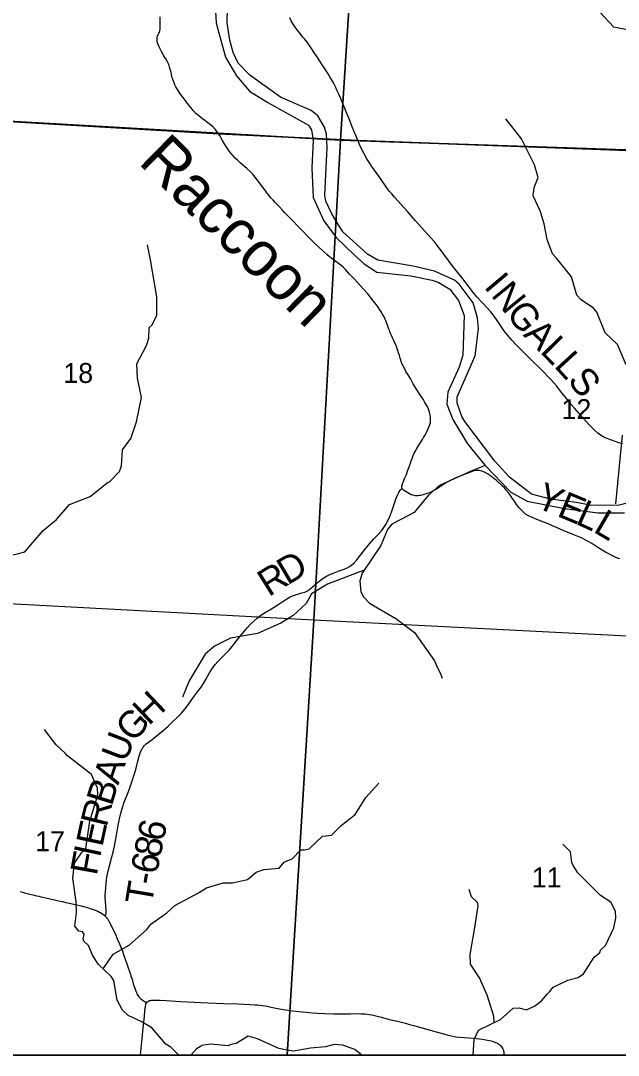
# Model space of a CAD drawing. Extents: x 0 to 34, y 0 to 22.
# Drawn here: x 24.638 to 25.892, y 14.1 to 16.271 of the extents above; entities that cross this region are included whole.
import ezdxf

# ---------------------------------------------------------------- set-up
doc = ezdxf.new("R2010")
doc.units = 0
for name, color, linetype in [('Default', 7, 'Continuous'), ('GM_X_County_Road', 7, 'Continuous'), ('GM_X_County_Road_Text', 7, 'Continuous'), ('GM_X_Major_River', 7, 'Continuous'), ('GM_X_Major_River_Text', 7, 'Continuous'), ('GM_X_Minor_River', 7, 'Continuous'), ('GM_X_Section', 7, 'Continuous'), ('GM_X_Section_Text', 7, 'Continuous'), ('GM_X_Township_Road', 7, 'Continuous'), ('GM_X_Township_Road_Text', 7, 'Continuous'), ('SH_Data', 7, 'Continuous'), ('SH_Text', 7, 'Continuous')]:
    doc.layers.add(name, color=color, linetype=linetype)

msp = doc.modelspace()

# ---------------------------------------------------------------- linework, layer by layer
at = {"layer": 'Default'}
msp.add_lwpolyline([(27.7198, 20.9), (23.5167, 20.9), (23.5167, 16.1239), (23.5888, 16.1195), (25.0535, 16.0331), (25.3458, 16.0191), (26.0811, 15.9921), (26.3691, 15.9829), (26.8773, 15.953), (26.8866, 15.9536), (26.8953, 15.9537)], dxfattribs=at)
for points in [[(23.5167, 16.1239), (23.5167, 14.1), (26.2331, 14.1), (26.29, 15.0246), (26.3153, 15.3279), (26.3625, 15.9099), (26.3691, 15.9829), (26.0811, 15.9921), (25.3458, 16.0191), (25.0535, 16.0331), (23.5888, 16.1195)], [(24.1517, 14.1), (25.1974, 14.1), (25.2534, 15.0128), (24.2076, 15.0689)], [(25.1974, 14.1), (26.2424, 14.1), (26.2944, 14.9601), (25.2534, 15.0128)]]:
    msp.add_lwpolyline(points, close=True, dxfattribs=at)
at = {"layer": 'GM_X_County_Road'}
for points in [[(25.346, 16.0186), (25.3384, 16.0361), (25.3322, 16.0517), (25.3286, 16.0609), (25.3252, 16.0696), (25.3227, 16.0758), (25.309, 16.1087), (25.3056, 16.1165), (25.3017, 16.1252), (25.2986, 16.132), (25.2957, 16.1375), (25.2921, 16.144), (25.287, 16.1526), (25.283, 16.1589), (25.2741, 16.173), (25.271, 16.1777), (25.2674, 16.1835), (25.259, 16.1966), (25.2562, 16.2007), (25.2452, 16.2165), (25.2389, 16.2254), (25.2333, 16.2324), (25.2303, 16.2364), (25.2268, 16.2408), (25.2217, 16.2469), (25.2181, 16.2512), (25.2139, 16.2573), (25.2097, 16.2636), (25.2056, 16.2704), (25.203, 16.2764)], [(25.7998, 15.4575), (25.7992, 15.4582), (25.7927, 15.4657), (25.783, 15.4778), (25.7709, 15.4936), (25.7619, 15.5048), (25.7517, 15.5165), (25.7436, 15.5251), (25.7371, 15.5319), (25.727, 15.5419), (25.7114, 15.5571), (25.6902, 15.578), (25.6784, 15.5899), (25.6686, 15.6003), (25.6612, 15.6086), (25.6575, 15.6134), (25.654, 15.6179), (25.6489, 15.6251), (25.644, 15.6324), (25.6377, 15.6414), (25.6317, 15.6505), (25.6245, 15.6595), (25.6166, 15.6684), (25.6043, 15.6815), (25.595, 15.6915), (25.5882, 15.6996), (25.5794, 15.7112), (25.5747, 15.7173), (25.5676, 15.7265), (25.5633, 15.7321), (25.5551, 15.7422), (25.5453, 15.7543), (25.5261, 15.7806), (25.5203, 15.7883), (25.5119, 15.7991), (25.5069, 15.8058), (25.4979, 15.8159), (25.4796, 15.836), (25.4664, 15.851), (25.4496, 15.8703), (25.4223, 15.9006), (25.4166, 15.9071), (25.412, 15.9123), (25.408, 15.9178), (25.4048, 15.9222), (25.3956, 15.9356), (25.3892, 15.9447), (25.3838, 15.9524), (25.3786, 15.9597), (25.3744, 15.9656), (25.3698, 15.9722), (25.3647, 15.9807), (25.3582, 15.9927), (25.3535, 16.0021), (25.3493, 16.0111), (25.346, 16.0186)], [(25.9013, 15.3826), (25.8912, 15.3859), (25.8871, 15.3872), (25.8754, 15.3913), (25.8685, 15.3939), (25.8617, 15.397), (25.8548, 15.401), (25.8489, 15.4054), (25.8423, 15.4111), (25.8323, 15.4212), (25.8181, 15.4369), (25.8099, 15.4462), (25.7998, 15.4575)], [(24.6371, 14.4437), (24.6419, 14.442), (24.6481, 14.4402), (24.652, 14.4392), (24.6571, 14.438), (24.6638, 14.4365), (24.6688, 14.4354), (24.6718, 14.4348), (24.6766, 14.4338), (24.6807, 14.4327), (24.6849, 14.4318), (24.6909, 14.4304), (24.7095, 14.4262), (24.7179, 14.4243), (24.7263, 14.4225), (24.7333, 14.4209), (24.7397, 14.4195), (24.7498, 14.4172), (24.7558, 14.4158), (24.7624, 14.4142), (24.769, 14.4125), (24.7761, 14.4105), (24.7883, 14.4065), (24.7945, 14.4043), (24.8, 14.4021), (24.8035, 14.4005), (24.8066, 14.3989), (24.8097, 14.3971), (24.8122, 14.3954), (24.8145, 14.3935), (24.8158, 14.3922), (24.8176, 14.3901), (24.8193, 14.3878), (24.8208, 14.3853), (24.8238, 14.3799), (24.8293, 14.3692), (24.8328, 14.362), (24.8369, 14.3539), (24.8408, 14.3445), (24.8454, 14.3342), (24.8469, 14.3305), (24.8485, 14.3264), (24.8501, 14.3224), (24.8523, 14.3167), (24.8542, 14.3114), (24.8608, 14.2922), (24.8644, 14.2817), (24.8683, 14.2703), (24.8696, 14.2662), (24.8718, 14.2597), (24.8745, 14.2503), (24.8758, 14.2461), (24.8776, 14.241), (24.8796, 14.2349), (24.8809, 14.2319), (24.8819, 14.2293), (24.8834, 14.2266), (24.8846, 14.2247), (24.886, 14.2229), (24.8874, 14.2211), (24.8898, 14.2189), (24.8934, 14.2162), (24.9012, 14.2109), (24.9024, 14.2101)], [(24.8894, 14.1), (24.893, 14.1352), (24.8953, 14.1575), (24.8978, 14.1816), (24.8988, 14.1938), (24.9001, 14.2034), (24.9006, 14.2057), (24.901, 14.2075), (24.9018, 14.2092), (24.9024, 14.2101)], [(24.9024, 14.2101), (24.9039, 14.2119), (24.9053, 14.213), (24.9069, 14.214), (24.9087, 14.2148), (24.9106, 14.2153), (24.9129, 14.2156), (24.9155, 14.2158), (24.9192, 14.2159), (24.9305, 14.2155), (24.9443, 14.2147), (24.9732, 14.2129), (25.0025, 14.2112), (25.0306, 14.2099), (25.0639, 14.2086), (25.0937, 14.2077), (25.1192, 14.2067), (25.1291, 14.2061), (25.1346, 14.2058), (25.1401, 14.2052), (25.1512, 14.2035), (25.167, 14.2006), (25.181, 14.1978), (25.1939, 14.1956), (25.2082, 14.1936), (25.2219, 14.1919), (25.2369, 14.1902), (25.2434, 14.1896), (25.2495, 14.1891), (25.2606, 14.1885), (25.2761, 14.1879), (25.2948, 14.1873), (25.3135, 14.187), (25.3302, 14.1873), (25.3424, 14.1875), (25.3526, 14.1872), (25.3599, 14.1869), (25.3661, 14.1864), (25.3703, 14.1858), (25.3751, 14.1849), (25.3915, 14.181), (25.4149, 14.1747), (25.4286, 14.1713), (25.4452, 14.1672), (25.4542, 14.1649), (25.4631, 14.1625), (25.4846, 14.1565), (25.5095, 14.1495), (25.5326, 14.1431), (25.5385, 14.1415), (25.5451, 14.14), (25.5513, 14.139), (25.5587, 14.1382), (25.5786, 14.1369), (25.5884, 14.136), (25.6006, 14.1346), (25.6068, 14.1338), (25.614, 14.1326), (25.6208, 14.1313), (25.6253, 14.1302), (25.6285, 14.1292), (25.6315, 14.1282), (25.6345, 14.127), (25.6371, 14.1259), (25.6393, 14.1247), (25.6415, 14.1233), (25.6434, 14.1218), (25.6454, 14.1198), (25.647, 14.1177), (25.6485, 14.1156), (25.6498, 14.1134), (25.6507, 14.1111), (25.6512, 14.109), (25.6515, 14.1067), (25.6518, 14.1035), (25.6519, 14.1)]]:
    msp.add_lwpolyline(points, dxfattribs=at)
at = {"layer": 'GM_X_Major_River'}
for points in [[(25.6326, 15.3467), (25.5696, 15.4298), (25.5635, 15.44), (25.5536, 15.4684), (25.5536, 15.4813), (25.5916, 15.5672), (25.5983, 15.6249), (25.5963, 15.6469), (25.5871, 15.6784), (25.5582, 15.7181), (25.548, 15.7261), (25.5062, 15.7453), (25.4619, 15.7557), (25.3876, 15.7684), (25.3656, 15.7808), (25.3143, 15.8277), (25.2979, 15.8538), (25.2907, 15.8656), (25.2781, 15.8921), (25.2766, 15.9046), (25.2812, 16.0048), (25.28, 16.0325), (25.2758, 16.0469), (25.2613, 16.0707), (25.2477, 16.0825), (25.1836, 16.1103), (25.1187, 16.156), (25.0943, 16.1817), (25.084, 16.2041), (25.0768, 16.2298), (25.0714, 16.2662), (25.0727, 16.3289)], [(25.0459, 16.3018), (25.0486, 16.2662), (25.0517, 16.2525), (25.0682, 16.1941), (25.091, 16.1547), (25.1184, 16.123), (25.1567, 16.0988), (25.2417, 16.0517), (25.2482, 16.0419), (25.2516, 16.0199), (25.2491, 15.9618), (25.2516, 15.8999), (25.2741, 15.8507), (25.3003, 15.8155), (25.3368, 15.7803), (25.3588, 15.7607), (25.3854, 15.7433), (25.457, 15.7356), (25.5017, 15.7259), (25.5139, 15.7222), (25.5385, 15.7074), (25.5568, 15.6836), (25.5686, 15.6518), (25.5658, 15.5687), (25.5583, 15.544), (25.5346, 15.4915), (25.532, 15.4661), (25.5446, 15.4339), (25.5755, 15.3827), (25.6126, 15.3376)], [(25.95, 15.2684), (25.8906, 15.2535), (25.8319, 15.254), (25.8043, 15.26), (25.7494, 15.2671), (25.71, 15.2772), (25.6634, 15.3127), (25.6326, 15.3467)], [(25.6126, 15.3376), (25.6665, 15.2812), (25.7006, 15.2624), (25.779, 15.2471), (25.8498, 15.2382), (25.9046, 15.2383)]]:
    msp.add_lwpolyline(points, dxfattribs=at)
at = {"layer": 'GM_X_Minor_River'}
for points in [[(26.1935, 16.3026), (26.1966, 16.2917), (26.1235, 16.2558), (26.036, 16.2415), (26.0085, 16.2365), (25.9717, 16.2351), (25.9486, 16.2438), (25.8827, 16.2572), (25.8535, 16.288), (25.8155, 16.3387), (25.8045, 16.3689)], [(25.9083, 15.5485), (25.8901, 15.5914), (25.8644, 15.6154), (25.8466, 15.6594), (25.8401, 15.6678), (25.814, 15.6853), (25.8049, 15.6948), (25.7939, 15.7335), (25.7624, 15.7723), (25.7537, 15.7814), (25.7424, 15.8114), (25.7367, 15.8441), (25.7291, 15.8673), (25.7272, 15.873), (25.7136, 15.9034), (25.7155, 15.9205), (25.7238, 15.9418), (25.7159, 15.9684), (25.689, 16.0228), (25.656, 16.0649)], [(24.8495, 15.3367), (24.8517, 15.3702), (24.8692, 15.3942), (24.8813, 15.4288), (24.8916, 15.4801), (24.8836, 15.5204), (24.8818, 15.5505), (24.9022, 15.5893), (24.9068, 15.6049), (24.9076, 15.6269), (24.914, 15.6326), (24.9239, 15.6528), (24.9235, 15.6916), (24.9103, 15.7687), (24.9042, 15.8007)], [(25.8868, 15.2567), (25.9007, 15.4013)], [(24.419, 15.219), (24.446, 15.2199), (24.4815, 15.1949), (24.4905, 15.1919), (24.5181, 15.1914), (24.5252, 15.1893), (24.5481, 15.1722), (24.5943, 15.1499), (24.6147, 15.1477), (24.6471, 15.1565), (24.6851, 15.2013), (24.7134, 15.2239), (24.7408, 15.2553), (24.784, 15.2725), (24.82, 15.301), (24.8246, 15.3031), (24.8453, 15.3249), (24.8495, 15.3368)], [(25.6126, 15.3376), (25.5843, 15.326), (25.5165, 15.2957), (25.4928, 15.2743), (25.4638, 15.2385), (25.452, 15.2323), (25.4168, 15.2143), (25.4074, 15.2032), (25.3936, 15.1698), (25.3549, 15.1115), (25.3496, 15.0955), (25.3521, 15.0727), (25.3574, 15.0617), (25.37, 15.0489), (25.4253, 15.0165), (25.4645, 14.9871), (25.5063, 14.9273), (25.5117, 14.9144), (25.5174, 14.9038), (25.5224, 14.8913)], [(25.3589, 15.1175), (25.2818, 15.0883), (25.2485, 15.068), (25.2368, 15.0478), (25.2097, 15.023), (25.184, 15.0069), (25.1348, 14.9846), (25.0783, 14.9749), (25.045, 14.9584), (25.025, 14.9419), (24.9919, 14.8856), (24.9777, 14.8513)], [(24.9701, 14.1), (24.9531, 14.1169), (24.9427, 14.1233), (24.9131, 14.1577), (24.8912, 14.1709), (24.864, 14.1832), (24.8515, 14.1946), (24.8408, 14.2158), (24.8334, 14.2567), (24.8279, 14.2652), (24.8015, 14.2904), (24.7896, 14.3086), (24.7808, 14.3305), (24.7705, 14.3392), (24.7695, 14.3445), (24.7717, 14.3543), (24.7677, 14.359), (24.7601, 14.3604), (24.7518, 14.3709), (24.7553, 14.3989), (24.7545, 14.4221), (24.7476, 14.4713), (24.7512, 14.5031), (24.7659, 14.5246), (24.7752, 14.5338), (24.7834, 14.5913), (24.8002, 14.6466), (24.7995, 14.6607), (24.7867, 14.6892), (24.7365, 14.7284), (24.7321, 14.7331), (24.7127, 14.7515), (24.6883, 14.7838)], [(24.8111, 14.2813), (24.8324, 14.3121), (24.8655, 14.3308), (24.9028, 14.3638), (24.911, 14.375), (24.945, 14.3986), (24.9614, 14.4144), (25.0113, 14.4412), (25.0279, 14.4517), (25.0633, 14.4616), (25.0826, 14.4621), (25.1142, 14.4691), (25.1324, 14.4845), (25.1481, 14.4897), (25.1807, 14.4924), (25.1917, 14.5057), (25.2074, 14.5121), (25.2261, 14.5312), (25.2329, 14.5314), (25.2435, 14.5329), (25.2716, 14.5598), (25.2905, 14.5618), (25.3104, 14.5824), (25.3398, 14.605), (25.3625, 14.6412), (25.3895, 14.6711)], [(25.5876, 14.1), (25.5876, 14.1001), (25.5894, 14.1334), (25.5987, 14.1525), (25.6447, 14.1753), (25.6715, 14.1988), (25.6836, 14.1995), (25.6986, 14.1956), (25.7159, 14.203), (25.7306, 14.214), (25.7435, 14.2287), (25.7478, 14.2332), (25.7549, 14.2428), (25.7859, 14.2574), (25.808, 14.2635), (25.8192, 14.2708), (25.8411, 14.3061), (25.8531, 14.3156), (25.8548, 14.3209), (25.8649, 14.3304), (25.8826, 14.3675), (25.8866, 14.3878), (25.8859, 14.4023), (25.8763, 14.4212), (25.8545, 14.4356), (25.8071, 14.4827), (25.797, 14.4985), (25.7945, 14.5043), (25.7914, 14.5268), (25.7753, 14.5433)], [(25.6312, 14.1686), (25.6306, 14.1822), (25.6168, 14.2263), (25.6005, 14.2626), (25.5817, 14.2909), (25.5812, 14.3114), (25.5908, 14.3684), (25.5979, 14.4138), (25.5962, 14.4203), (25.5841, 14.4328), (25.5789, 14.4482)], [(25.354, 14.1), (25.3391, 14.1125), (25.3137, 14.1216), (25.296, 14.1227), (25.2775, 14.1177), (25.2461, 14.1153), (25.2102, 14.1088), (25.2004, 14.1103), (25.1796, 14.1144), (25.1349, 14.1345), (25.1153, 14.1401), (25.0903, 14.1245), (25.0794, 14.1225), (25.0737, 14.1199), (25.037, 14.1232), (25.0174, 14.1209), (25.0151, 14.1182), (25.0072, 14.1133), (24.9952, 14.1)]]:
    msp.add_lwpolyline(points, dxfattribs=at)
at = {"layer": 'GM_X_Section'}
for points in [[(24.3357, 17.1007), (25.3722, 17.0086), (25.3091, 16.0203), (24.2716, 16.0795)], [(26.4248, 16.9831), (26.3613, 15.9846), (25.3091, 16.0203), (25.3722, 17.0086), (25.8848, 17.0085)], [(24.2716, 16.0795), (25.3091, 16.0203), (25.2534, 15.0128), (24.2076, 15.0689)], [(25.3091, 16.0203), (26.3613, 15.9846), (26.3734, 15.9843), (26.2944, 14.9601), (25.2534, 15.0128)]]:
    msp.add_lwpolyline(points, close=True, dxfattribs=at)
at = {"layer": 'GM_X_Township_Road'}
for points in [[(24.9421, 16.1912), (24.9387, 16.1966), (24.9335, 16.2063), (24.9287, 16.2155), (24.9258, 16.222), (24.9248, 16.2263), (24.9244, 16.2307), (24.9247, 16.2352), (24.9253, 16.2383), (24.9267, 16.2418), (24.9282, 16.2446), (24.9293, 16.2467), (24.9303, 16.2496), (24.9308, 16.2532), (24.9308, 16.2599), (24.9307, 16.2705), (24.9306, 16.2785)], [(25.0526, 16.0342), (25.0499, 16.0383), (25.0461, 16.0431), (25.0418, 16.0475), (25.0366, 16.0519), (25.0278, 16.0587), (25.0258, 16.0602), (25.0223, 16.0627), (25.0124, 16.0702), (25.0059, 16.076), (25.0002, 16.0819), (24.9952, 16.0882), (24.9885, 16.0972), (24.9833, 16.1041), (24.9783, 16.1105), (24.9733, 16.1168), (24.9708, 16.1205), (24.9684, 16.1241), (24.9659, 16.1284), (24.9638, 16.1322), (24.9618, 16.1363), (24.96, 16.1401), (24.9571, 16.1477), (24.9562, 16.1508), (24.9552, 16.1543), (24.9545, 16.1578), (24.9536, 16.1616), (24.9525, 16.167), (24.9507, 16.173), (24.9488, 16.1785), (24.9461, 16.1842), (24.9427, 16.1903), (24.9421, 16.1912)], [(25.8952, 15.1415), (25.887, 15.1444), (25.8785, 15.1484), (25.8717, 15.152), (25.8647, 15.1557), (25.8491, 15.1657), (25.8364, 15.1737), (25.8261, 15.1796), (25.816, 15.1847), (25.7987, 15.1918), (25.7762, 15.2013), (25.7413, 15.2164), (25.7299, 15.2209), (25.7176, 15.2257), (25.7135, 15.2273), (25.7101, 15.2287), (25.7033, 15.232), (25.6975, 15.2356), (25.6936, 15.2387), (25.6899, 15.2421), (25.6844, 15.248), (25.6814, 15.2519), (25.6784, 15.2558), (25.6738, 15.2625), (25.6705, 15.2671), (25.6669, 15.2724), (25.6619, 15.2794), (25.6569, 15.2856), (25.6528, 15.2903), (25.6488, 15.2943), (25.6453, 15.2976), (25.6395, 15.3032), (25.6354, 15.3067), (25.6311, 15.3104), (25.6238, 15.316), (25.6176, 15.3199), (25.611, 15.3232), (25.6058, 15.3253), (25.6005, 15.3267), (25.5963, 15.3271), (25.592, 15.3268), (25.5867, 15.3255), (25.578, 15.3223), (25.5653, 15.3172), (25.5494, 15.3107), (25.5394, 15.3057), (25.5292, 15.3002), (25.5092, 15.2869), (25.5015, 15.2828), (25.494, 15.2796), (25.489, 15.278), (25.484, 15.2763), (25.4802, 15.2754), (25.4773, 15.2747), (25.4742, 15.2742), (25.4711, 15.2738), (25.466, 15.2738), (25.4629, 15.2743), (25.4603, 15.2749), (25.4575, 15.2761), (25.4437, 15.2845), (25.4416, 15.286), (25.4399, 15.2874), (25.4391, 15.2885), (25.4385, 15.2896), (25.438, 15.2911), (25.4379, 15.293), (25.4381, 15.2949), (25.4383, 15.2967), (25.4389, 15.2986), (25.4411, 15.3042), (25.4422, 15.3067), (25.4448, 15.3126), (25.4474, 15.3187), (25.4507, 15.3278), (25.4534, 15.3349), (25.4552, 15.3404), (25.4575, 15.3473), (25.4592, 15.3523), (25.461, 15.3573), (25.4636, 15.3636), (25.4654, 15.3669), (25.4682, 15.3717), (25.4734, 15.3802), (25.4761, 15.3843), (25.4781, 15.3875), (25.481, 15.3922), (25.4832, 15.3959), (25.4861, 15.4007), (25.4908, 15.4094), (25.494, 15.4161), (25.4959, 15.4213), (25.4976, 15.4279), (25.4982, 15.4333), (25.4982, 15.4382), (25.4975, 15.4436), (25.4959, 15.4496), (25.4938, 15.4553), (25.4908, 15.4618), (25.4863, 15.4697), (25.4822, 15.4768), (25.4743, 15.4887), (25.4619, 15.5089), (25.4559, 15.5197), (25.4496, 15.5297), (25.4472, 15.5334), (25.4439, 15.5399), (25.4431, 15.5415), (25.4419, 15.5437), (25.4396, 15.548), (25.4385, 15.5501), (25.4375, 15.5521), (25.4363, 15.5556), (25.4354, 15.5591), (25.4344, 15.5628), (25.4327, 15.5682), (25.431, 15.574), (25.4294, 15.5787), (25.428, 15.5824), (25.4263, 15.5868), (25.4201, 15.6009), (25.4181, 15.6055), (25.416, 15.6104), (25.4148, 15.6131), (25.4136, 15.6161), (25.4123, 15.6193), (25.4107, 15.6232), (25.4075, 15.6321), (25.4044, 15.6406), (25.4005, 15.649), (25.3972, 15.6552), (25.3945, 15.6596), (25.3918, 15.6642), (25.3881, 15.6695), (25.3847, 15.6744), (25.3814, 15.6786), (25.3764, 15.6852), (25.3668, 15.6974), (25.3564, 15.7084), (25.3385, 15.7283), (25.3281, 15.7387), (25.3199, 15.7483), (25.3147, 15.7538), (25.3097, 15.7579), (25.3028, 15.7629), (25.2993, 15.7655), (25.296, 15.7681), (25.2927, 15.7705), (25.2882, 15.7739), (25.2863, 15.7754), (25.2807, 15.7803), (25.2794, 15.7815), (25.2729, 15.7874), (25.2532, 15.8053), (25.2457, 15.8128), (25.225, 15.8342), (25.2045, 15.8556), (25.1988, 15.8613), (25.1919, 15.8685), (25.1868, 15.8739), (25.1802, 15.8806), (25.173, 15.8882), (25.1676, 15.894), (25.1632, 15.899), (25.158, 15.9056), (25.1548, 15.9098), (25.1523, 15.9131), (25.1456, 15.922), (25.1427, 15.9257), (25.139, 15.9304), (25.1342, 15.9366), (25.1294, 15.943), (25.1252, 15.9483), (25.1201, 15.9537), (25.1128, 15.9603), (25.1033, 15.9684), (25.0987, 15.9725), (25.0937, 15.9772), (25.0885, 15.9825), (25.0836, 15.9879), (25.0766, 15.9963), (25.0704, 16.0045), (25.0665, 16.0106), (25.0617, 16.0191), (25.055, 16.0307), (25.0537, 16.0326), (25.0526, 16.0342)], [(24.8158, 14.3922), (24.817, 14.3956), (24.8174, 14.3978), (24.8176, 14.4001), (24.8175, 14.4028), (24.816, 14.4241), (24.8158, 14.4301), (24.8158, 14.4361), (24.8168, 14.4515), (24.8176, 14.4607), (24.8193, 14.4742), (24.8217, 14.487), (24.8243, 14.4978), (24.8288, 14.5133), (24.8322, 14.526), (24.8348, 14.5388), (24.839, 14.562), (24.8418, 14.5786), (24.8454, 14.5962), (24.8483, 14.6083), (24.8517, 14.6201), (24.8556, 14.6312), (24.8645, 14.6536), (24.8682, 14.6635), (24.8716, 14.6735), (24.8743, 14.6818), (24.8769, 14.6907), (24.8802, 14.7027), (24.8833, 14.714), (24.887, 14.7278), (24.8898, 14.7367), (24.8921, 14.7417), (24.8947, 14.7459), (24.8982, 14.7501), (24.9017, 14.7535), (24.9142, 14.7626), (24.922, 14.7687), (24.9368, 14.7811), (24.9474, 14.7907), (24.9574, 14.8), (24.9662, 14.8086), (24.9696, 14.8118), (24.9748, 14.8171), (24.9825, 14.826), (24.9897, 14.8354), (24.9958, 14.8441), (25.0031, 14.8541), (25.0072, 14.8596), (25.0146, 14.8696), (25.0181, 14.8747), (25.0214, 14.88), (25.0265, 14.8886), (25.0345, 14.9026), (25.0409, 14.9124), (25.0465, 14.9199), (25.0518, 14.9259), (25.0661, 14.9404), (25.0755, 14.9503), (25.084, 14.9602), (25.0989, 14.9792), (25.107, 14.9893), (25.1139, 14.9973), (25.1199, 15.0036), (25.1277, 15.0115), (25.1341, 15.0174), (25.1385, 15.0208), (25.1441, 15.0247), (25.1662, 15.0382), (25.1818, 15.0482), (25.1901, 15.0537), (25.1963, 15.0577), (25.2033, 15.0616), (25.2106, 15.0649), (25.2187, 15.0678), (25.2277, 15.0701), (25.2344, 15.0718), (25.2384, 15.0736), (25.2427, 15.0762), (25.2457, 15.0785), (25.2499, 15.082), (25.2537, 15.0855), (25.2603, 15.0915), (25.2664, 15.0964), (25.2729, 15.1009), (25.2797, 15.1051), (25.2869, 15.1088), (25.296, 15.1125), (25.3065, 15.1163), (25.3171, 15.1199), (25.3228, 15.1224), (25.3277, 15.1252), (25.3322, 15.1284), (25.3378, 15.1334), (25.3432, 15.1394), (25.3509, 15.1491), (25.3599, 15.1609), (25.3702, 15.1733), (25.3793, 15.1833), (25.3866, 15.191), (25.3949, 15.2003), (25.4002, 15.2072), (25.4044, 15.2134), (25.4086, 15.2211), (25.4126, 15.2302), (25.417, 15.2418), (25.4228, 15.2602), (25.4257, 15.269), (25.4292, 15.2769), (25.4312, 15.2806), (25.4333, 15.2842), (25.436, 15.2873), (25.4385, 15.2896)]]:
    msp.add_lwpolyline(points, dxfattribs=at)
at = {"layer": 'SH_Data'}
msp.add_lwpolyline([(23.5167, 20.9), (30.3167, 20.9), (30.3167, 14.1), (23.5167, 14.1)], close=True, dxfattribs=at)
at = {"layer": 'SH_Text'}
msp.add_lwpolyline([(30.3167, 20.9), (23.5167, 20.9), (23.5167, 14.1), (29.5051, 14.1)], dxfattribs=at)

# ---------------------------------------------------------------- texts
at = {"layer": 'GM_X_County_Road_Text'}
for s, rotation, p in [('I', 310.1619, (25.6085, 15.7119)), ('N', 309.1815, (25.6234, 15.6942)), ('G', 307.9566, (25.6548, 15.6557)), ('A', 315.0572, (25.6907, 15.6106)), ('L', 314.6167, (25.726, 15.5753)), ('L', 312.4173, (25.7554, 15.5455)), ('S', 309.6705, (25.7836, 15.5147))]:
    msp.add_text(s, height=0.0568, rotation=rotation, dxfattribs=at).set_placement(p)
at = {"layer": 'GM_X_Major_River_Text'}
msp.add_text('Raccoon', height=0.0947, rotation=315.5119, dxfattribs=at).set_placement((24.8827, 15.9724))
at = {"layer": 'GM_X_Section_Text'}
for s, p in [('18', (24.7279, 15.5106)), ('12', (25.7729, 15.4347)), ('17', (24.6687, 14.5282)), ('11', (25.7104, 14.4523))]:
    msp.add_text(s, height=0.04186, rotation=0, dxfattribs=at).set_placement(p)
at = {"layer": 'GM_X_Township_Road_Text'}
for s, rotation, p in [('Y', 337.4034, (25.7149, 15.2513)), ('E', 337.3228, (25.7611, 15.2321)), ('L', 335.5532, (25.7999, 15.2159)), ('L', 329.6834, (25.8372, 15.1991)), ('D', 30.5858, (25.1978, 15.0854)), ('R', 31.935, (25.1585, 15.0609)), ('H', 43.4942, (24.9068, 14.7902)), ('G', 47.346, (24.8737, 14.7542)), ('U', 69.0963, (24.8588, 14.7123)), ('A', 71.307, (24.843, 14.6655)), ('B', 72.6895, (24.8292, 14.6213)), ('R', 76.1223, (24.8183, 14.5768)), ('E', 77.7836, (24.8094, 14.5357)), ('6', 78.0221, (24.9376, 14.5463)), ('8', 78.5482, (24.9307, 14.5122)), ('F', 79.6956, (24.7977, 14.4757)), ('I', 77.9606, (24.8045, 14.513)), ('6', 79.2004, (24.9242, 14.4779)), ('-', 79.9493, (24.9201, 14.4552)), ('T', 80.3939, (24.9131, 14.4134))]:
    msp.add_text(s, height=0.0568, rotation=rotation, dxfattribs=at).set_placement(p)

doc.saveas('drawing.dxf')
